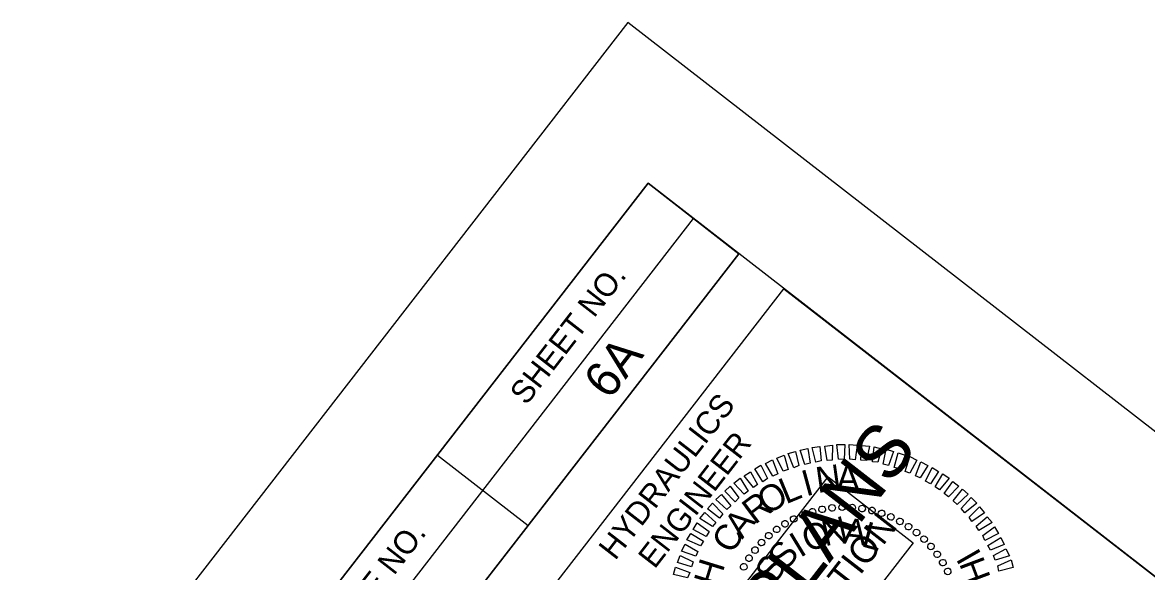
# Model space of a CAD drawing. Extents: x 2013373 to 2015284, y 444589 to 446636.
# Drawn here: x 2014282.4 to 2014527.7, y 446515.8 to 446635.5 of the extents above; entities that cross this region are included whole.
import ezdxf

# ---------------------------------------------------------------- set-up
doc = ezdxf.new("R2010")
doc.units = 0
for name, color, linetype in [('Sheet Data Field CELL', 7, 'Continuous'), ('Sheet Plan And Profile CELL', 7, 'Continuous'), ('Sheet Plot Border Outside CELL', 7, 'Continuous'), ('Sheet Professional Seal CELL', 7, 'Continuous'), ('Sheet Profile Grid Minor CELL', 7, 'Continuous'), ('Sheet Sticker Incomplete CELL', 7, 'Continuous')]:
    doc.layers.add(name, color=color, linetype=linetype)

msp = doc.modelspace()

# ---------------------------------------------------------------- linework, layer by layer
at = {"layer": 'Sheet Plan And Profile CELL'}
for p, q in [((2014306.25, 446434.66), (2014428.85, 446592.74)), ((2014316.13, 446427), (2014438.73, 446585.08)), ((2014373.01, 446541.14), (2014392.76, 446525.82))]:
    msp.add_line(p, q, dxfattribs=at)
for points in [[(2014418.93, 446600.43), (2013499.68, 445415.12), (2014329.4, 444771.64), (2015248.65, 445956.96)], [(2014296.33, 446442.35), (2014418.93, 446600.43), (2014438.73, 446585.08), (2014316.13, 446427)], [(2014387.32, 446498.4), (2014448.6, 446577.42), (2014537.5, 446508.48), (2014476.22, 446429.46)]]:
    msp.add_lwpolyline(points, close=True, dxfattribs=at)
at = {"layer": 'Sheet Plot Border Outside CELL'}
msp.add_lwpolyline([(2014241.91, 444618.03), (2015283.73, 445961.39), (2014414.5, 446635.51), (2013372.67, 445292.15)], close=True, dxfattribs=at)
at = {"layer": 'Sheet Professional Seal CELL'}
for p, q in [((2014456.94, 446529.35), (2014456.94, 446529.35)), ((2014459.08, 446529.66), (2014459.08, 446529.66)), ((2014461.3, 446529.83), (2014461.3, 446529.83)), ((2014463.45, 446529.75), (2014463.45, 446529.75)), ((2014465.66, 446529.49), (2014465.66, 446529.49)), ((2014450.73, 446527.21), (2014450.73, 446527.21)), ((2014452.71, 446528.14), (2014452.71, 446528.14)), ((2014454.8, 446528.79), (2014454.8, 446528.79)), ((2014467.81, 446529.08), (2014467.81, 446529.08)), ((2014469.88, 446528.49), (2014469.88, 446528.49)), ((2014471.91, 446527.68), (2014471.91, 446527.68)), ((2014446.95, 446524.95), (2014446.95, 446524.95)), ((2014448.79, 446526.18), (2014448.79, 446526.18)), ((2014473.89, 446526.65), (2014473.89, 446526.65)), ((2014475.78, 446525.57), (2014475.78, 446525.57)), ((2014477.54, 446524.26), (2014477.54, 446524.26)), ((2014443.71, 446522.08), (2014443.71, 446522.08)), ((2014445.31, 446523.57), (2014445.31, 446523.57)), ((2014479.19, 446522.79), (2014479.19, 446522.79)), ((2014442.25, 446520.44), (2014442.25, 446520.44)), ((2014480.68, 446521.2), (2014480.68, 446521.2)), ((2014482.06, 446519.55), (2014482.06, 446519.55)), ((2014440.94, 446518.67), (2014440.94, 446518.67)), ((2014483.29, 446517.71), (2014483.29, 446517.71)), ((2014439.86, 446516.78), (2014439.86, 446516.78)), ((2014484.32, 446515.78), (2014484.32, 446515.78))]:
    msp.add_line(p, q, dxfattribs=at)
for points in [[(2014450.71, 446538.36), (2014449.49, 446541.52), (2014451.12, 446541.91), (2014451.86, 446538.86)], [(2014453.15, 446539.06), (2014452.11, 446542.21), (2014453.78, 446542.56), (2014454.29, 446539.38)], [(2014455.54, 446539.61), (2014454.74, 446542.83), (2014456.42, 446543.04), (2014456.71, 446539.91)], [(2014458.03, 446539.96), (2014457.49, 446543.1), (2014459.17, 446543.32), (2014459.12, 446540.07)], [(2014460.52, 446540.24), (2014460.15, 446543.44), (2014461.86, 446543.44), (2014461.74, 446540.18)], [(2014462.98, 446540.23), (2014462.82, 446543.46), (2014464.55, 446543.32), (2014464.1, 446540.13)], [(2014465.4, 446540.01), (2014465.52, 446543.26), (2014467.29, 446543.1), (2014466.62, 446539.95)], [(2014467.93, 446539.68), (2014468.27, 446542.97), (2014469.89, 446542.53), (2014469.05, 446539.58)], [(2014470.24, 446539.16), (2014470.87, 446542.41), (2014472.53, 446541.94), (2014471.42, 446538.88)], [(2014472.65, 446538.43), (2014473.49, 446541.63), (2014475.06, 446541.12), (2014473.79, 446538.18)], [(2014444, 446535.34), (2014442.21, 446538.18), (2014443.55, 446538.92), (2014444.98, 446536.03)], [(2014446.13, 446536.54), (2014444.56, 446539.33), (2014446.07, 446540.13), (2014447.24, 446537.07)], [(2014448.45, 446537.65), (2014447.02, 446540.46), (2014448.61, 446541.13), (2014449.5, 446538.03)], [(2014475.04, 446537.59), (2014476.09, 446540.82), (2014477.58, 446540.05), (2014476.08, 446537.22)], [(2014477.3, 446536.59), (2014478.48, 446539.66), (2014480.01, 446538.86), (2014478.32, 446536.19)], [(2014441.91, 446534.11), (2014439.92, 446536.61), (2014441.26, 446537.52), (2014442.83, 446534.73)], [(2014479.48, 446535.48), (2014480.91, 446538.47), (2014482.35, 446537.55), (2014480.55, 446534.9)], [(2014481.56, 446534.24), (2014483.23, 446537.06), (2014484.64, 446536.09), (2014482.57, 446533.59)], [(2014437.93, 446530.94), (2014435.67, 446533.25), (2014436.88, 446534.4), (2014438.78, 446531.79)], [(2014439.92, 446532.62), (2014437.66, 446535), (2014439.02, 446536.1), (2014440.77, 446533.29)], [(2014483.56, 446532.75), (2014485.44, 446535.41), (2014486.78, 446534.37), (2014484.51, 446532.02)], [(2014436.14, 446529.29), (2014433.69, 446531.44), (2014434.94, 446532.56), (2014437.03, 446530.11)], [(2014485.51, 446531.18), (2014487.58, 446533.69), (2014488.82, 446532.6), (2014486.39, 446530.37)], [(2014487.25, 446529.51), (2014489.45, 446531.86), (2014490.67, 446530.66), (2014488.05, 446528.58)], [(2014434.49, 446527.4), (2014431.92, 446529.39), (2014432.97, 446530.67), (2014435.26, 446528.32)], [(2014489.02, 446527.63), (2014491.24, 446529.84), (2014492.37, 446528.52), (2014489.6, 446526.67)], [(2014432.98, 446525.54), (2014430.26, 446527.33), (2014431.31, 446528.6), (2014433.75, 446526.45)], [(2014490.52, 446525.65), (2014492.93, 446527.7), (2014494.02, 446526.41), (2014491.1, 446524.69)], [(2014431.64, 446523.41), (2014428.78, 446524.93), (2014429.66, 446526.4), (2014432.26, 446524.45)], [(2014491.96, 446523.58), (2014494.57, 446525.48), (2014495.39, 446524.02), (2014492.45, 446522.51)], [(2014429.37, 446519.09), (2014426.24, 446520.19), (2014427.01, 446521.75), (2014429.82, 446520.08)], [(2014430.41, 446521.33), (2014427.39, 446522.66), (2014428.28, 446524.05), (2014431.03, 446522.37)], [(2014493.08, 446521.45), (2014495.89, 446523.19), (2014496.65, 446521.65), (2014493.64, 446520.38)], [(2014494.29, 446519.25), (2014497.02, 446520.73), (2014497.79, 446519.19), (2014494.67, 446518.19)], [(2014428.42, 446516.8), (2014425.34, 446517.73), (2014425.94, 446519.23), (2014428.78, 446517.84)], [(2014495.25, 446516.98), (2014498.15, 446518.27), (2014498.64, 446516.63), (2014495.47, 446515.8)], [(2014427.55, 446514.37), (2014424.46, 446515.12), (2014424.91, 446516.68), (2014428.08, 446515.54)]]:
    msp.add_lwpolyline(points, close=True, dxfattribs=at)
for centre, major_axis in [((2014454.81, 446528.78), (-0.201, 0.691)), ((2014456.93, 446529.3), (-0.14, 0.706)), ((2014459.1, 446529.63), (-0.078, 0.716)), ((2014461.28, 446529.77), (-0.015, 0.72)), ((2014463.47, 446529.72), (0.048, 0.718)), ((2014465.64, 446529.48), (0.11, 0.712)), ((2014467.79, 446529.06), (0.172, 0.699)), ((2014469.89, 446528.44), (0.232, 0.682)), ((2014448.81, 446526.15), (-0.373, 0.616)), ((2014450.73, 446527.2), (-0.318, 0.646)), ((2014452.73, 446528.08), (-0.26, 0.671)), ((2014471.93, 446527.65), (0.29, 0.659)), ((2014473.89, 446526.68), (0.347, 0.631)), ((2014445.28, 446523.57), (-0.474, 0.542)), ((2014446.99, 446524.94), (-0.425, 0.581)), ((2014475.76, 446525.54), (0.4, 0.598)), ((2014477.52, 446524.25), (0.451, 0.561)), ((2014443.7, 446522.06), (-0.52, 0.498)), ((2014479.16, 446522.8), (0.498, 0.52)), ((2014480.68, 446521.22), (0.542, 0.474)), ((2014440.96, 446518.65), (-0.598, 0.4)), ((2014442.26, 446520.41), (-0.561, 0.451)), ((2014482.04, 446519.51), (0.581, 0.425)), ((2014439.83, 446516.78), (-0.631, 0.347)), ((2014483.26, 446517.69), (0.616, 0.373)), ((2014484.31, 446515.77), (0.646, 0.318))]:
    msp.add_ellipse(centre, major_axis=major_axis, ratio=0.999708, dxfattribs=at)
at = {"layer": 'Sheet Sticker Incomplete CELL'}
msp.add_lwpolyline([(2014386.73, 446405.85), (2014368.16, 446420.25), (2014458.24, 446536.41), (2014476.81, 446522.01)], close=True, dxfattribs=at)

# ---------------------------------------------------------------- texts
at = {"layer": 'Sheet Data Field CELL'}
msp.add_text('6A', height=7.75, rotation=52.2051, dxfattribs=at).set_placement((2014410.47, 446552.98))
at = {"layer": 'Sheet Plan And Profile CELL'}
for s, height, p in [('SHEET NO.', 5, (2014392.36, 446551.82)), ('HYDRAULICS', 5, (2014411.75, 446517.99)), ('ENGINEER', 5, (2014420.36, 446516.12)), ('PROJECT REFERENCE NO.', 5.0001, (2014316.81, 446454.56))]:
    msp.add_text(s, height=height, rotation=52.2051, dxfattribs=at).set_placement(p)
at = {"layer": 'Sheet Professional Seal CELL'}
for s, rotation, p in [('N', 8.024, (2014455.93, 446532.86)), ('A', 0.8223, (2014460.07, 446533.38)), ('I', 15.2252, (2014453.39, 446532.11)), ('O', 29.6263, (2014444.85, 446528.04)), ('L', 22.426, (2014449.01, 446530.38)), ('R', 36.8262, (2014442.21, 446525.85)), ('A', 51.2254, (2014439.47, 446522.65)), ('N', 12.6817, (2014457.54, 446521.23)), ('A', 353.9654, (2014461.34, 446521.89)), ('C', 58.425, (2014437.29, 446519.35)), ('O', 22.0386, (2014453.91, 446519.81)), ('L', 344.606, (2014465.27, 446521.31)), ('S', 50.1055, (2014448.94, 446515.69)), ('I', 31.3947, (2014452.13, 446518.66)), ('H', 72.8246, (2014434.21, 446512.12)), ('S', 59.4607, (2014446.78, 446512.81))]:
    msp.add_text(s, height=5.64, rotation=rotation, dxfattribs=at).set_placement(p)
at = {"layer": 'Sheet Profile Grid Minor CELL'}
for s, rotation, p in [('I', 119.7977, (2014491.79, 446519.48)), ('H', 110.5529, (2014493.78, 446514.47))]:
    msp.add_text(s, height=5.5, rotation=rotation, dxfattribs=at).set_placement(p)
at = {"layer": 'Sheet Sticker Incomplete CELL'}
for s, height, p in [('INCOMPLETE PLANS', 11.52, (2014382.97, 446420.09)), ('DO NOT USE FOR R/W ACQUISITION', 5.76, (2014390.45, 446418.4))]:
    msp.add_text(s, height=height, rotation=52.2051, dxfattribs=at).set_placement(p)

doc.saveas('drawing.dxf')
